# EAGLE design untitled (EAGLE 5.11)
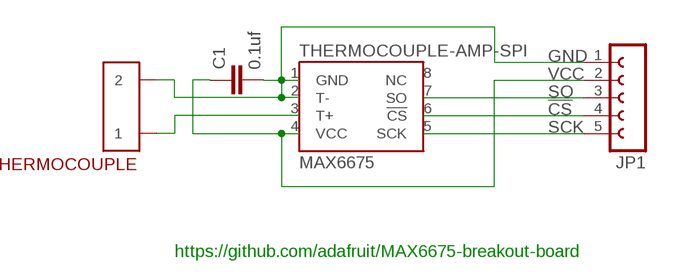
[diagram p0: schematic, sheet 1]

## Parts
C1  0.1uf  C-EU050-024X044  [C050-024X044]
JP1  FE05-1  [FE05-1]
THERMOCOUPLE  SCREW-CLAMP-1.5  [SCREW-CLAMP-1.5]
THERMOCOUPLE-AMP-SPI  MAX6675  [8SOIC]

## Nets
!CS: JP1.4 THERMOCOUPLE-AMP-SPI.6(!CS)
GND: C1.2 JP1.1 THERMOCOUPLE-AMP-SPI.1(GND) THERMOCOUPLE-AMP-SPI.2(T-) THERMOCOUPLE.2
N$1: THERMOCOUPLE-AMP-SPI.3(T+) THERMOCOUPLE.1
SCK: JP1.5 THERMOCOUPLE-AMP-SPI.5(SCK)
SO: JP1.3 THERMOCOUPLE-AMP-SPI.7(SO)
VCC: C1.1 JP1.2 THERMOCOUPLE-AMP-SPI.4(VCC)
Unconnected: THERMOCOUPLE-AMP-SPI.8(NC)

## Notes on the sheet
- https://github.com/adafruit/MAX6675-breakout-board

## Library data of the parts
C1 = rcl:C-EU: CAPACITOR, European symbol
JP1 = con-lsta:FE05-1: FEMALE HEADER; OC_FARNELL: unknown; OC_NEWARK: unknown
THERMOCOUPLE = trl:SCREW-CLAMP-1.5
THERMOCOUPLE-AMP-SPI = trl:MAX6675

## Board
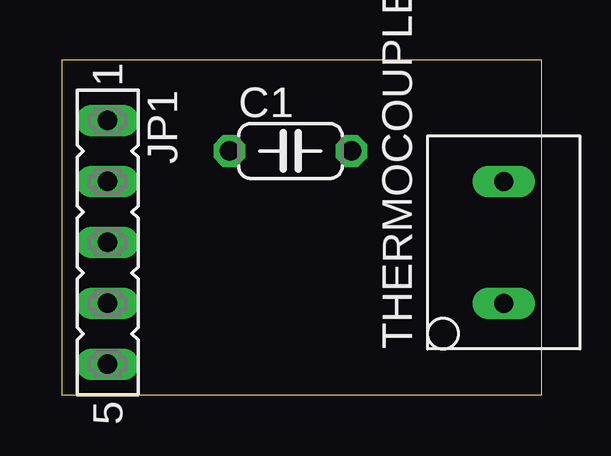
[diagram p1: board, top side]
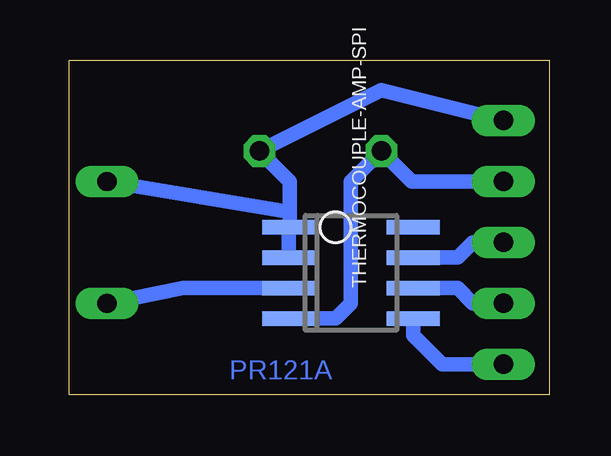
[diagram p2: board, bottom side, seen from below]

Size 19.99 x 13.96 mm. Coordinates in mm from the lower left corner, seen from the top.
Outline: 0,0 19.99,0 19.99,13.96 0,13.96 0,0
Copper layers (1*16): Top 0.035mm / dielectric 1.5mm / Bottom 0.035mm
Design rules "default": minimum track width 10mil, minimum drill 24mil, track to track 8mil, track to pad 8mil, pad to pad 8mil, via to via 8mil, smd to smd 8mil, copper to edge 40mil, drill to drill 8mil, minimum pad ring 10mil, minimum via ring 8mil, stop-mask expansion 4mil, vias tented up to drill 0mil, thermal gap 10mil

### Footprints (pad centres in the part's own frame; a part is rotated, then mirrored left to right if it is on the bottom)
C050-024X044 = drill 0.813 octagon: 1 -2.54,0; 2 2.54,0
FE05-1 = drill 0.813 long: 1 -5.08,0; 2 -2.54,0; 3 0,0; 4 2.54,0; 5 5.08,0
SCREW-CLAMP-1.5 = drill 0.8 long: 1 -1.27,0; 2 3.81,0
8SOIC = smd 0.6 x 2.2: 1 -1.905,-2.6; 2 -0.635,-2.6; 3 0.635,-2.6; 4 1.905,-2.6; 5 1.905,2.6; 6 0.635,2.6; 7 -0.635,2.6; 8 -1.905,2.6

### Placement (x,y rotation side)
C1  9.53,10.16 0 top
JP1  1.91,6.35 270 top
THERMOCOUPLE  18.41,5.08 90 top
THERMOCOUPLE-AMP-SPI  8.26,5.08 270 bottom

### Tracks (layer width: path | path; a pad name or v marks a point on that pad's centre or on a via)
!CS
  Bottom 0.61: JP1.4 3.17,3.81 3.81,4.45 THERMOCOUPLE-AMP-SPI.6
GND
  Bottom 0.61: JP1.1 6.99,12.7 C1.2 10.79,8.89 10.79,7.62 | 10.79,7.62 10.79,7.04 THERMOCOUPLE-AMP-SPI.1 THERMOCOUPLE-AMP-SPI.2 | 10.79,7.62 THERMOCOUPLE.2
N$1
  Bottom 0.61: THERMOCOUPLE.1 15.24,4.45 14.61,4.45 THERMOCOUPLE-AMP-SPI.3
SCK
  Bottom 0.61: THERMOCOUPLE-AMP-SPI.5 5.66,2.48 4.45,1.27 JP1.5
SO
  Bottom 0.61: THERMOCOUPLE-AMP-SPI.7 3.81,5.71 3.17,6.35 JP1.3
VCC
  Bottom 0.61: JP1.2 5.71,8.89 C1.1 8.26,8.89 8.26,3.81 8.89,3.17 THERMOCOUPLE-AMP-SPI.4

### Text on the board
Bottom: PR121A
